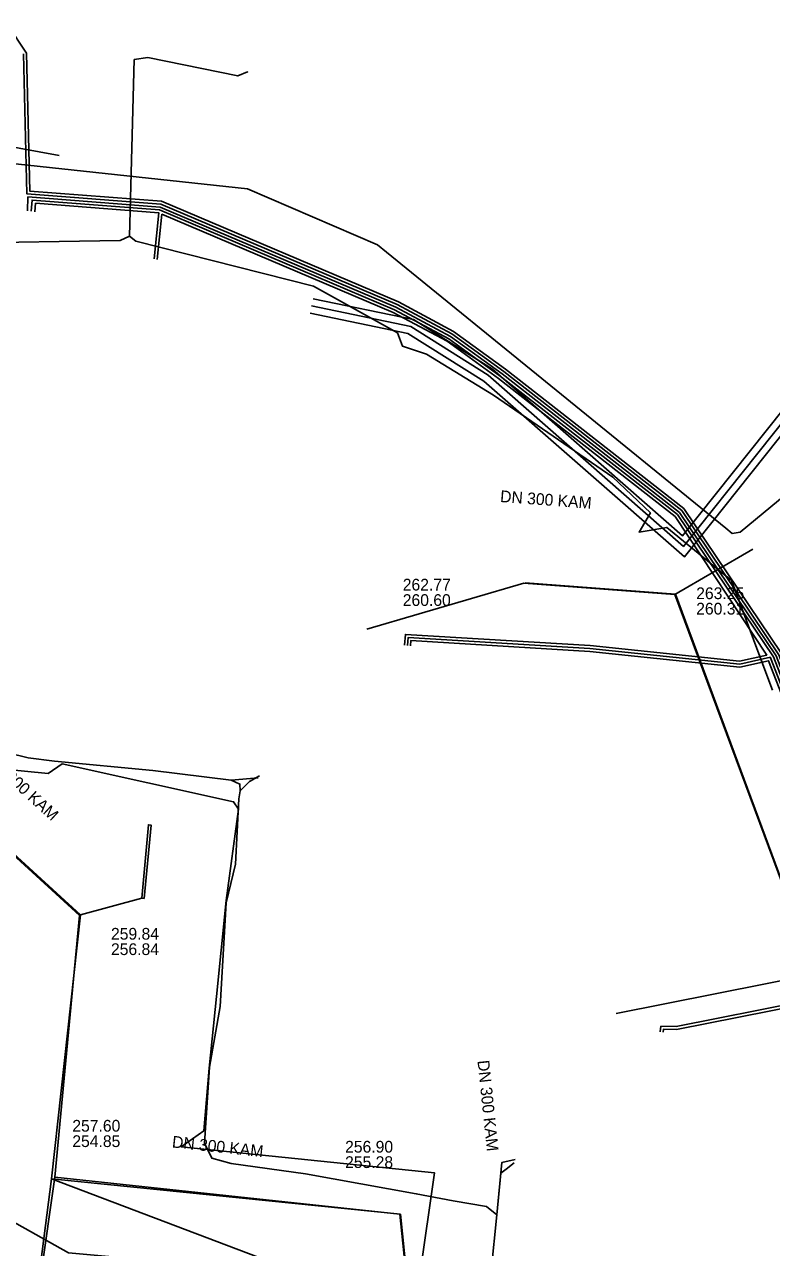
# Model space of a CAD drawing. Extents: x -598233 to -596890, y -1157848 to -1156431.
# Drawn here: x -597226.2 to -597175.3, y -1157309.7 to -1157226.3 of the extents above; entities that cross this region are included whole.
import ezdxf

# ---------------------------------------------------------------- set-up
doc = ezdxf.new("R2010")
doc.units = 0
for name, color, linetype in [('Vrstva 1', 7, 'Continuous'), ('Vrstva 12', 7, 'Continuous'), ('Vrstva 13', 7, 'Continuous'), ('Vrstva 25', 7, 'Continuous'), ('Vrstva 26', 7, 'Continuous'), ('Vrstva 3', 7, 'Continuous'), ('Vrstva 4', 7, 'Continuous'), ('Vrstva 42', 7, 'Continuous'), ('Vrstva 55', 7, 'Continuous'), ('Vrstva 58', 7, 'Continuous')]:
    doc.layers.add(name, color=color, linetype=linetype)

msp = doc.modelspace()

# ---------------------------------------------------------------- linework, layer by layer
at = {"layer": 'Vrstva 1'}
for p, q in [((-597192.13, -1157264.37), (-597181.89, -1157265.14)), ((-597181.89, -1157265.14), (-597172.32, -1157291)), ((-597236.71, -1157274.04), (-597222.49, -1157287.05)), ((-597222.49, -1157287.05), (-597224.18, -1157304.89)), ((-597224.18, -1157304.89), (-597225.95, -1157317.21)), ((-597200.67, -1157307.41), (-597224.18, -1157304.89)), ((-597198.709, -1157326.167), (-597200.67, -1157307.41))]:
    msp.add_line(p, q, dxfattribs=at)
for points in [[(-597223.88, -1157235.24), (-597238.03, -1157232.64), (-597238.43, -1157232.84)], [(-597176.61, -1157262.08), (-597181.93, -1157265.16)], [(-597192.21, -1157264.39), (-597202.92, -1157267.52)], [(-597192.21, -1157264.39), (-597181.93, -1157265.16)], [(-597181.93, -1157265.16), (-597172.33, -1157291.03)], [(-597222.43, -1157287), (-597236.69, -1157273.95)], [(-597222.43, -1157287), (-597218.26, -1157285.87)], [(-597224.4, -1157305.01), (-597222.43, -1157287)], [(-597185.92, -1157293.73), (-597172.33, -1157291.03)], [(-597224.4, -1157305.01), (-597225.98, -1157317.21)], [(-597200.63, -1157307.41), (-597224.4, -1157305.01)], [(-597210.32, -1157310.35), (-597224.4, -1157305.01)], [(-597198.71, -1157326.17), (-597200.63, -1157307.41)]]:
    msp.add_lwpolyline(points, dxfattribs=at)
at = {"layer": 'Vrstva 12'}
for points in [[(-597211.55, -1157278.55), (-597211.56, -1157278.09), (-597212.17, -1157277.83), (-597217.5, -1157277.17), (-597224.19, -1157276.53), (-597226, -1157276.3), (-597229.98, -1157275.33), (-597231.15, -1157274.93), (-597231.52, -1157274.26), (-597231.29, -1157271.77), (-597230.8, -1157266.44), (-597229.98, -1157259.62), (-597229.53, -1157252.9), (-597229.59, -1157252.29)], [(-597211.55, -1157278.55), (-597210.92, -1157277.92), (-597210.24, -1157277.52)], [(-597211.63, -1157279.09), (-597211.55, -1157278.55)], [(-597194.07, -1157307.45), (-597194.76, -1157306.88), (-597197.03, -1157306.5), (-597199.55, -1157306.02), (-597207.1, -1157304.65), (-597212.17, -1157303.96), (-597213.49, -1157303.6), (-597213.97, -1157302.58), (-597213.64, -1157297.38), (-597212.92, -1157293.25), (-597212.5, -1157286.18), (-597211.87, -1157283.56), (-597211.63, -1157279.09)], [(-597194.07, -1157307.45), (-597193.71, -1157303.88), (-597192.81, -1157303.68)], [(-597195.67, -1157324.08), (-597195.25, -1157319.54), (-597194.36, -1157311.86), (-597194.44, -1157311.27), (-597194.07, -1157307.45)]]:
    msp.add_lwpolyline(points, dxfattribs=at)
at = {"layer": 'Vrstva 13'}
msp.add_lwpolyline([(-597160.937, -1157240.503), (-597159.898, -1157245.23), (-597159.723, -1157245.966), (-597159.864, -1157246.341), (-597177.485, -1157260.915), (-597178.025, -1157261.009), (-597178.45, -1157260.645), (-597201.579, -1157241.826), (-597202.195, -1157241.336), (-597211.039, -1157237.51), (-597229.002, -1157235.583), (-597234.374, -1157240.247), (-597236.19, -1157243.911), (-597236.228, -1157244.361), (-597237.086, -1157252.029), (-597237.578, -1157256.749), (-597240.111, -1157280.207), (-597240.983, -1157288.356), (-597237.8, -1157298.905), (-597233.253, -1157304.426), (-597223.241, -1157310.053), (-597212.984, -1157310.978), (-597205.805, -1157311.676)], dxfattribs=at)
at = {"layer": 'Vrstva 25'}
msp.add_lwpolyline([(-597166.148, -1157242.8), (-597181.341, -1157261.886), (-597194.648, -1157250.216), (-597199.923, -1157246.895), (-597206.682, -1157245.491)], dxfattribs=at)
at = {"layer": 'Vrstva 26'}
for points in [[(-597166.539, -1157242.489), (-597181.406, -1157261.164), (-597194.348, -1157249.814), (-597199.733, -1157246.424), (-597206.58, -1157245.001)], [(-597165.757, -1157243.112), (-597181.276, -1157262.608), (-597194.948, -1157250.618), (-597200.113, -1157247.366), (-597206.784, -1157245.981)]]:
    msp.add_lwpolyline(points, dxfattribs=at)
at = {"layer": 'Vrstva 3'}
msp.add_lwpolyline([(-597218.26, -1157285.87), (-597217.8, -1157280.86), (-597217.62, -1157280.89), (-597218.1, -1157285.88)], close=True, dxfattribs=at)
at = {"layer": 'Vrstva 42'}
for points in [[(-597227.393, -1157226.308), (-597226.111, -1157228.254), (-597225.882, -1157237.668), (-597216.907, -1157238.361), (-597200.768, -1157245.226), (-597197.011, -1157247.228), (-597193.465, -1157249.8), (-597181.307, -1157259.311), (-597174.66, -1157269.199), (-597168.313, -1157285.522), (-597165.173, -1157293.315), (-597160.086, -1157306.169), (-597159.824, -1157306.415), (-597153.523, -1157303.704), (-597149.246, -1157303.191), (-597148.927, -1157303.375), (-597148.685, -1157303.514), (-597148.263, -1157303.757), (-597147.393, -1157306.117), (-597147.57, -1157307.042), (-597148.241, -1157307.976)], [(-597226.31, -1157228.316), (-597226.078, -1157237.854), (-597216.955, -1157238.558), (-597200.855, -1157245.406), (-597197.118, -1157247.398), (-597193.586, -1157249.96), (-597181.456, -1157259.449), (-597174.846, -1157269.271), (-597168.499, -1157285.596), (-597165.358, -1157293.389), (-597160.256, -1157306.284), (-597159.865, -1157306.651), (-597153.471, -1157303.899), (-597149.285, -1157303.398), (-597149.064, -1157303.526), (-597148.889, -1157303.627), (-597148.426, -1157303.894), (-597147.6, -1157306.134), (-597147.758, -1157306.961), (-597148.325, -1157307.751)], [(-597226.046, -1157239.014), (-597226.006, -1157238.062), (-597217.003, -1157238.755), (-597200.941, -1157245.587), (-597197.224, -1157247.568), (-597193.706, -1157250.12), (-597181.605, -1157259.586), (-597175.033, -1157269.344), (-597168.685, -1157285.669), (-597165.544, -1157293.463), (-597160.425, -1157306.399), (-597159.906, -1157306.886), (-597153.418, -1157304.094), (-597149.33, -1157303.604), (-597149.141, -1157303.713), (-597148.966, -1157303.814), (-597148.589, -1157304.031), (-597147.807, -1157306.151), (-597147.946, -1157306.88), (-597148.409, -1157307.524)], [(-597225.786, -1157239.046), (-597225.729, -1157238.281), (-597217.051, -1157238.952), (-597201.027, -1157245.768), (-597197.33, -1157247.738), (-597193.826, -1157250.28), (-597181.754, -1157259.723), (-597175.219, -1157269.416), (-597168.871, -1157285.743), (-597165.73, -1157293.537), (-597160.595, -1157306.515), (-597159.948, -1157307.122), (-597153.366, -1157304.29), (-597149.373, -1157303.81), (-597149.219, -1157303.899), (-597149.044, -1157304), (-597148.751, -1157304.169), (-597148.013, -1157306.169), (-597148.134, -1157306.8), (-597148.494, -1157307.301)], [(-597217.415, -1157242.292), (-597217.099, -1157239.149), (-597225.485, -1157238.493), (-597225.534, -1157239.071)], [(-597200.357, -1157268.62), (-597200.293, -1157267.887), (-597187.697, -1157268.654), (-597177.523, -1157269.708), (-597175.663, -1157269.295), (-597181.903, -1157259.861), (-597193.947, -1157250.44), (-597197.437, -1157247.908), (-597201.114, -1157245.948), (-597216.876, -1157239.244), (-597217.204, -1157242.324)], [(-597200.154, -1157268.639), (-597200.107, -1157268.099), (-597187.713, -1157268.853), (-597177.511, -1157269.91), (-597175.423, -1157269.446), (-597175.406, -1157269.489), (-597169.057, -1157285.816), (-597165.916, -1157293.611), (-597160.764, -1157306.63), (-597159.989, -1157307.357), (-597153.313, -1157304.485), (-597149.416, -1157304.016), (-597149.296, -1157304.085), (-597149.121, -1157304.186), (-597148.914, -1157304.306), (-597148.22, -1157306.186), (-597148.322, -1157306.719), (-597148.581, -1157307.079)], [(-597182.931, -1157294.981), (-597182.88, -1157294.602), (-597181.836, -1157294.613), (-597173.358, -1157292.945), (-597168.607, -1157292.608), (-597166.287, -1157293.224), (-597166.33, -1157293.117), (-597169.243, -1157285.89), (-597175.547, -1157269.678), (-597177.499, -1157270.112), (-597187.729, -1157269.052), (-597199.921, -1157268.311), (-597199.941, -1157268.663)], [(-597182.733, -1157295.007), (-597182.706, -1157294.804), (-597181.818, -1157294.813), (-597173.332, -1157293.143), (-597168.627, -1157292.81), (-597166.193, -1157293.456), (-597166.101, -1157293.685), (-597160.934, -1157306.745), (-597160.03, -1157307.593), (-597153.261, -1157304.68), (-597149.458, -1157304.224), (-597149.373, -1157304.273), (-597149.199, -1157304.373), (-597149.077, -1157304.443), (-597148.427, -1157306.203), (-597148.51, -1157306.638), (-597148.667, -1157306.856)]]:
    msp.add_lwpolyline(points, dxfattribs=at)
at = {"layer": 'Vrstva 55'}
for points in [[(-597175.28, -1157271.69), (-597176.073, -1157269.569), (-597178.08, -1157264.21), (-597182.48, -1157260.59), (-597184.37, -1157260.91), (-597183.6, -1157259.59), (-597186.16, -1157257.17), (-597194.28, -1157251.58), (-597198.85, -1157248.79), (-597200.48, -1157248.24), (-597200.82, -1157247.33), (-597206.55, -1157244.15), (-597218.66, -1157241.09), (-597219.1, -1157240.74), (-597218.77, -1157228.7), (-597217.84, -1157228.55), (-597211.71, -1157229.82), (-597211.04, -1157229.54), (-597211.71, -1157229.82), (-597217.84, -1157228.55), (-597218.77, -1157228.7), (-597219.1, -1157240.74), (-597219.73, -1157241.04), (-597230.8, -1157241.22)], [(-597232.94, -1157276.56), (-597224.63, -1157277.36), (-597223.67, -1157276.72), (-597212, -1157279.29), (-597211.67, -1157279.8), (-597212.509, -1157286.022), (-597213.168, -1157292.575), (-597213.66, -1157297.46), (-597214.02, -1157301.72), (-597215.56, -1157302.83), (-597198.3, -1157304.6), (-597199.313, -1157311.556)]]:
    msp.add_lwpolyline(points, dxfattribs=at)
at = {"layer": 'Vrstva 58'}
for points in [[(-597212.17, -1157277.83), (-597217.5, -1157277.17), (-597224.19, -1157276.53), (-597226, -1157276.3), (-597229.98, -1157275.33), (-597231.15, -1157274.93), (-597231.52, -1157274.26), (-597231.29, -1157271.77), (-597230.8, -1157266.44), (-597229.98, -1157259.62), (-597229.53, -1157252.9), (-597229.59, -1157252.29)], [(-597212.17, -1157277.83), (-597210.317, -1157277.666)], [(-597212.17, -1157277.83), (-597210.317, -1157277.666)], [(-597194.07, -1157307.45), (-597194.76, -1157306.88), (-597197.03, -1157306.5), (-597199.55, -1157306.02), (-597207.1, -1157304.65), (-597212.17, -1157303.96), (-597213.49, -1157303.6), (-597213.97, -1157302.58), (-597213.64, -1157297.38), (-597212.92, -1157293.25), (-597212.5, -1157286.18), (-597211.87, -1157283.56), (-597211.63, -1157279.09), (-597211.55, -1157278.55), (-597211.56, -1157278.09), (-597212.17, -1157277.83)], [(-597194.07, -1157307.45), (-597193.785, -1157304.624), (-597193.43, -1157304.34), (-597192.885, -1157303.904)], [(-597190.537, -1157326.279), (-597192.02, -1157326.05), (-597192.43, -1157325.96), (-597195.21, -1157325.42), (-597195.55, -1157325.23), (-597195.73, -1157324.8), (-597195.67, -1157324.08), (-597195.25, -1157319.54), (-597194.36, -1157311.86), (-597194.44, -1157311.27), (-597194.07, -1157307.45)]]:
    msp.add_lwpolyline(points, dxfattribs=at)

# ---------------------------------------------------------------- texts
at = {"layer": 'Vrstva 4'}
for rotation, p in [(355.6922, (-597193.856, -1157258.859)), (317.53321, (-597228.986, -1157276.438)), (275.99376, (-597195.382, -1157296.95)), (353.85873, (-597216.22, -1157302.857))]:
    msp.add_text('DN 300 KAM', height=0.8, rotation=rotation, dxfattribs=at).set_placement(p)
for s, p in [('262.77', (-597200.47, -1157264.897)), ('260.60', (-597200.47, -1157265.947)), ('263.25', (-597180.476, -1157265.483)), ('260.31', (-597180.476, -1157266.533)), ('259.84', (-597220.351, -1157288.695)), ('256.84', (-597220.351, -1157289.745)), ('257.60', (-597222.986, -1157301.783)), ('254.85', (-597222.986, -1157302.833)), ('256.90', (-597204.399, -1157303.212)), ('255.28', (-597204.399, -1157304.262))]:
    msp.add_text(s, height=0.8, dxfattribs=at).set_placement(p)

doc.saveas('drawing.dxf')
